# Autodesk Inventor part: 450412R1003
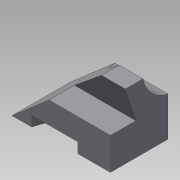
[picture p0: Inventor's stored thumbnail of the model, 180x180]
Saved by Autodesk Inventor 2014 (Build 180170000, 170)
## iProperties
Created: 2015-04
Part Number: 450412R1003
Material: Generic
Document SubType Name: Modeling
Designer: 203-07
Density: 1 g/cm^3
Appearance: Default
Author: 203-07
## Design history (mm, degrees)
sketch "스케치2"
  geometry: L1 (67.5, 0)-(-67.5, 0); L2 (-67.5, 0)-(-67.5, 89); L3 (-67.5, 89)-(-34.883, 89); L4 (-34.883, 89)-(67.5, 0); 2 further points
  constraints: 8 end point, 2 perpendicular, 1 coincident, 1 horizontal, 1 midpoint
  dimensions: "d0" = 135 distance of L1.start L1.end; "d1" = 89 distance of L1.end L2.end; "d2" = 139 deg angle of L1 L4
extrude "돌출1" new body sketch "스케치2" distance "d3" = 79; taper "d4" = 0 deg
sketch "스케치3"
  geometry: L1 (135, 0)-(0, 0) reference; L2 (0, 79)-(135, 79) reference; L3 (108, 0)-(82.331, 79); L4 (44.912, 0)-(19.244, 79); L5 (82.331, 79)-(19.244, 79); L6 (108, 0)-(44.912, 0); 1 further point
  constraints: 8 end point, 4 point on line, 2 collinear, 1 parallel
  dimensions: "d5" = 72 deg angle of L4 L2; "d6" = 27 distance of L3.start L1.start; "d7" = 60 distance between parallel lines of L4 L3
extrude "돌출2" cut sketch "스케치3" distance "d8" = 14; taper "d9" = 0 deg
sketch "스케치4"
  geometry: L1 (89, 0)-(0, 0) reference; L2 (89, 0)-(89, 79) reference; L3 (0, 79)-(89, 79) reference; L4 (0, 0)-(0, 79) reference; L5 (0, 20.379)-(45, 35); L6 (45, 35)-(45, 0); L7 (45, 0)-(0, 0); L8 (0, 0)-(0, 20.379); C1 r 44 at (-8, 88)
  constraints: 8 end point, 2 collinear, 2 point on line, 1 centre point, 1 perpendicular
  dimensions: "d10" = 44 radius of C1; "d11" = 8 distance from line of C1.centre L4; "d12" = 9 distance from line of C1.centre L3; "d13" = 72 deg angle of L6 L5; "d14" = 44 distance between parallel lines of L2 L6; "d15" = 35 distance of L5.end L6.end
extrude "돌출3" cut sketch "스케치4" stored distance "d16" = 14; taper "d17" = 0 deg
node "솔리드1"
